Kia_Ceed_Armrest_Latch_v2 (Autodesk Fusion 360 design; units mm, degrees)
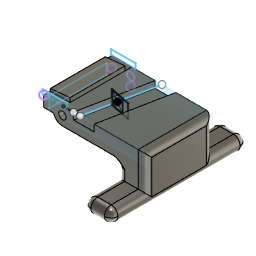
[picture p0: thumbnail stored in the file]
sketch "Sketch1" plane through (0, 0, 0) normal (0, 1, 0) x axis (1, 0, 0)
  line L1 (24.4506, -2.4661) -> (-5.5494, -2.4661)
  line L2 (24.4506, 0.6939) -> (24.4506, -2.4661)
  line L3 (-5.5494, 0.6939) -> (24.4506, 0.6939)
  line L4 (-5.5494, -2.4661) -> (-5.5494, 0.6939)
  line L5 (0.3006, -3.1561) -> (-5.5494, -3.1561)
  line L6 (0.3006, -2.4661) -> (0.3006, -3.1561)
  line L7 (-5.5494, -2.4661) -> (0.3006, -2.4661)
  line L8 (-5.5494, -3.1561) -> (-5.5494, -2.4661)
  line L9 (0.3006, -3.7461) -> (0.3006, -3.1561)
  line L10 (-5.5494, -3.1561) -> (0.3006, -3.7461)
  line L11 (16.4506, 7.6939) -> (24.4506, 7.6939)
  line L12 (4.3, 0.6939) -> (-3.0354, 0.6939)
  line L13 (4.3, -1.4) -> (4.3, 0.6939)
  line L14 (-3.0354, -1.4) -> (4.3, -1.4)
  line L15 (-3.0354, 0.6939) -> (-3.0354, -1.4)
  line L16 (24.4506, 7.6939) -> (16.4506, 7.6939)
  line L17 (24.4506, 11.6939) -> (24.4506, 7.6939)
  line L18 (16.4506, 11.6939) -> (24.4506, 11.6939)
  line L19 (16.4506, 7.6939) -> (16.4506, 11.6939)
  line L20 (24.4506, 9.6939) -> (24.4506, 0.6939)
  line L21 (24.9943, 2.7) -> (-0.0057, 2.7)
  line L22 (24.4506, 7.6939) -> (16.4506, 7.6939)
  line L23 (24.4506, 2.6939) -> (24.4506, 7.6939)
  line L24 (16.4506, 2.6939) -> (24.4506, 2.6939)
  line L25 (16.4506, 7.6939) -> (16.4506, 2.6939)
  circle C1 centre (0, 0) radius 2.7
  circle C2 centre (0, 0) radius 1.1
  point P1 (0, 0)
  point P13 (0, 0)
  point P14 (0, 0)
  point P15 (-3.0354, 0.6939)
  point P23 (-0.0057, 2.7)
  point P2 (-5.5494, -2.4661)
  point P3 (24.4506, -2.4661)
  point P5 (-5.5494, 0.6939)
  point P6 (-5.5494, -3.1561)
  point P7 (0.3006, -3.1561)
  point P9 (-5.5494, -2.4661)
  point P10 (0.3006, -3.7461)
  point P4 (24.4506, 0.6939)
  point P11 (24.4506, 7.6939)
  point P12 (16.4506, 7.6939)
  point P19 (24.4506, 7.6939)
  point P21 (16.4506, 11.6939)
  point P22 (24.4506, 9.6939)
  point P24 (24.9943, 2.7)
  point P25 (24.4506, 7.6939)
  point P27 (16.4506, 2.6939)
  horizontal L1
  vertical L2
  horizontal L3
  vertical L4
  horizontal L5
  vertical L6
  horizontal L7
  vertical L8
  perpendicular L5 L9
  coincident P1 P13
  coincident P1 P14
  horizontal L12
  vertical L13
  horizontal L14
  vertical L15
  coincident L3 P15
  horizontal L16
  vertical L17
  horizontal L18
  vertical L19
  perpendicular L3 L20
  coincident C1 P23
  perpendicular L20 L21
  horizontal L22
  vertical L23
  horizontal L24
  vertical L25
  dimension "d2" distance P2 P3 = 30
  dimension "d3" distance P2 P5 = 3.16
  dimension "d6" distance P6 P7 = 5.85
  dimension "d7" distance P6 P9 = 0.69
  dimension "d8" distance P7 P10 = 0.59
  dimension "d69" distance P4 P11 = 7
  dimension "d70" distance P11 P12 = 8
  dimension "d78" diameter C1 = 5.4
  dimension "d79" diameter C2 = 2.2
  dimension "d92" distance P12 P19 = 8
  dimension "d93" distance P12 P21 = 4
  dimension "d94" distance P4 P22 = 9
  dimension "d95" distance P23 P24 = 25
  dimension "d98" distance P12 P25 = 8
  dimension "d99" distance P12 P27 = 5
sketch "Sketch3" plane through (-5.5494, 0, 0) normal (-1, 0, 0) x axis (0, -1, 0)
  line L1 (-1.6288, 1.3075) -> (-18.6288, 1.3075)
  line L2 (-1.6288, -1.6925) -> (-1.6288, 1.3075)
  line L3 (-18.6288, -1.6925) -> (-1.6288, -1.6925)
  line L4 (-18.6288, 1.3075) -> (-18.6288, -1.6925)
  point P2 (-18.6288, 1.3075)
  point P3 (-1.6288, 1.3075)
  point P5 (-18.6288, -1.6925)
  horizontal L1
  vertical L2
  horizontal L3
  vertical L4
  dimension "d19" distance P2 P3 = 17
  dimension "d20" distance P2 P5 = 3
extrude "Extrude4" new body sketch "Sketch1" profile of L1 L2 L3 L4 L5 L6 L7 L8 L9 L10 along normal blind 20.21
extrude "Extrude5" cut sketch "Sketch3" against normal blind 3.81
sketch "Sketch6" plane through (0, 20.21, 0) normal (0, 1, 0) x axis (-1, 0, 0)
  line L1 (-24.4506, 2.4661) -> (5.5494, 2.4661)
  line L2 (-24.4506, -0.6939) -> (-24.4506, 2.4661)
  line L3 (5.5494, -0.6939) -> (-24.4506, -0.6939)
  line L4 (5.5494, 2.4661) -> (5.5494, -0.6939)
  line L5 (5.8, 2.4819) -> (-1.4771, 2.4819)
  line L6 (5.8, 4.0158) -> (5.8, 2.4819)
  line L7 (-1.4771, 4.0158) -> (5.8, 4.0158)
  line L8 (-1.4771, 2.4819) -> (-1.4771, 4.0158)
  horizontal L5
  vertical L6
  horizontal L7
  vertical L8
extrude "Extrude6" cut sketch "Sketch6" profile of L4 L5 L8 against normal blind 1.965
sketch "Sketch10" plane through (0, 0, 0) normal (0, -1, 0) x axis (1, 0, 0)
  line L1 (-5.5494, -0.6939) -> (-5.5494, 2.4661)
  line L2 (24.4506, -0.6939) -> (-5.5494, -0.6939)
  line L3 (24.4506, 2.4661) -> (24.4506, -0.6939)
  line L4 (-5.5494, 2.4661) -> (24.4506, 2.4661)
  line L5 (-5.8, 2.4819) -> (1.409, 2.4819)
  line L6 (-5.8, 3.8158) -> (-5.8, 2.4819)
  line L7 (1.409, 3.8158) -> (-5.8, 3.8158)
  line L8 (1.409, 2.4819) -> (1.409, 3.8158)
  horizontal L5
  vertical L6
  horizontal L7
  vertical L8
extrude "Extrude7" cut sketch "Sketch10" profile of L1 L5 L8 against normal blind 1.965
copy_paste_bodies "CopyPasteBodies1"
extrude "Extrude8" cut blind 40
extrude "Extrude11" new body sketch "Sketch1" + "Sketch10" profile of S1:L1 S1:L2 S1:L3 S1:L4 S1:L5 S1:L6 S1:L7 S1:L8 S1:L9 S1:L10 S2:L1 S2:L2 S2:L3 S2:L4 S2:L5 blind 20.21
extrude "Extrude12" cut sketch "Sketch3" against normal blind 3.24
extrude "Extrude13" cut blind 40
extrude "Extrude14" cut sketch "Sketch1" profile of L1 L5 L6 L7 L8 L9 L10 along normal blind 1.965
extrude "Extrude15" cut sketch "Sketch6" profile of L4 L5 L6 L7 L8 against normal blind 1.965
extrude "Extrude19" add sketch "Sketch1" profile of L3 C1 C2 L12 L13 L14 along normal blind 20.21
extrude "Extrude20" add sketch "Sketch1" profile of L3 C1 C2 L12 along normal blind 20.21
extrude "Extrude21" cut sketch "Sketch1" profile of L3 C2 L12 along normal blind 30
extrude "Extrude22" add sketch "Sketch3" against normal blind 4
extrude "Extrude23" cut sketch "Sketch3" against normal blind 3.45
extrude "Extrude24" add sketch "Sketch1" profile of L3 C1 L12 L20 L21 along normal blind 20.21
extrude "Extrude25" add sketch "Sketch1" profile of L11 L16 L20 L21 L22 L23 L25 along normal blind 20.21
extrude "Extrude26" new body sketch "Sketch1" profile of L11 L16 L17 L18 L19 L20 L22 against normal blind 10
extrude "Extrude27" add sketch "Sketch1" profile of L11 L16 L17 L18 L19 L20 L22 along normal blind 20.21
extrude "Extrude28" add of existing geometry blind 10
extrude "Extrude29" cut sketch "Sketch1" profile of L3 C2 L12 along normal blind 60
copy_paste_bodies "CopyPasteBodies1"
copy_paste_bodies "CopyPasteBodies2"
copy_paste_bodies "CopyPasteBodies3"
copy_paste_bodies "CopyPasteBodies4"
combine "Combine1"
fillet "Fillet1" radius 2
sketch "Sketch13" plane through (0, 0, 0) normal (0, 1, 0) x axis (1, 0, 0)
sketch "Sketch14" plane through (0, 20.21, 0) normal (0, 1, 0) x axis (-1, 0, 0)
  line L1 (-0.0033, -2.7) -> (-14.9865, -2.7)
  line L2 (5.5494, -0.6939) -> (2.6093, -0.6939)
  line L3 (5.5494, 2.4819) -> (5.5494, -0.6939)
  line L4 (-0.3006, 2.4819) -> (5.5494, 2.4819)
  line L5 (-0.3006, 2.4661) -> (-0.3006, 2.4819)
  line L6 (-22.4506, 2.4661) -> (-0.3006, 2.4661)
  line L7 (-22.4506, -7.6939) -> (-22.4506, 2.4661)
  line L8 (-18.4506, -7.6939) -> (-22.4506, -7.6939)
  line L9 (-18.4506, -4.7) -> (-18.4506, -7.6939)
  curve K1 (-18.4506, -4.7) -> (-14.9865, -2.7)
  arc A1 centre (0, 0) radius 2.7 clockwise from (2.6093, -0.6939) to (-0.0033, -2.7)
  circle C1 centre (0, 0) radius 1.1
sketch "Sketch15" plane through (0, 0, 2.4661) normal (0, 0, 1) x axis (-1, 0, 0)
  line L1 (-22.4506, -20.21) -> (-22.4506, 0)
  line L2 (-0.3006, -20.21) -> (-22.4506, -20.21)
  line L3 (-0.3006, -1.965) -> (-0.3006, -20.21)
  line L4 (5.5494, -1.965) -> (-0.3006, -1.965)
  line L5 (5.5494, 0) -> (5.5494, -1.965)
  line L6 (-22.4506, 0) -> (5.5494, 0)
  line L7 (-3.3006, 0) -> (-0.3006, 0)
  line L8 (-9.3006, -20.21) -> (-5.3006, 0)
  point P8 (-0.3006, 0)
  point P9 (-3.3006, 0)
  point P10 (-5.3006, 0)
  coincident L6 P8
  perpendicular L3 L7
  dimension "d117" distance P8 P9 = 3
  dimension "d118" distance P9 P10 = 2
work_plane "WorkPlane1" PathDistance 0.5601
sketch "Sketch16" plane through (7.1141, 9.1626, 2.4661) normal (0.1942, 0.981, 0) x axis (-0.981, 0.1942, 0)
  line L1 (2, 2) -> (-2, 2)
  line L2 (2, -2) -> (2, 2)
  line L3 (-2, -2) -> (2, -2)
  line L4 (-2, 2) -> (-2, -2)
  line L5 (2, -2) -> (-2, 2)
  line L6 (-2, -2) -> (2, 2)
  line L7 (-4, 2) -> (2, 2)
  line L8 (-4, -2) -> (-4, 2)
  line L9 (2, -2) -> (-4, -2)
  line L10 (2, 2) -> (2, -2)
  point P6 (0, 0)
  point P1 (0, 0)
  point P4 (2, -2)
  point P5 (-2, -2)
  point P3 (2, 2)
  point P7 (-4, 2)
  point P9 (2, -2)
  horizontal L1
  perpendicular L1 L2
  parallel L1 L3
  parallel L2 L4
  coincident L5 P6
  coincident L6 P6
  coincident P1 P6
  horizontal L7
  vertical L8
  horizontal L9
  vertical L10
  dimension "d121" distance P4 P5 = 4
  dimension "d122" distance P3 P4 = 4
  dimension "d123" distance P3 P7 = 6
  dimension "d124" distance P3 P9 = 4
extrude "Extrude1" cut sketch "Sketch16" profile of L1 L2 L3 L4 L7 L8 L9 L10 distance 15
extrude "Extrude2" add sketch "Sketch1" profile of L3 C2 L12 along normal blind 20.21
extrude "Extrude3" cut sketch "Sketch1" profile of L3 C2 L12 along normal blind 20.21
extrude "Extrude4" add sketch "Sketch1" profile of L3 C2 L12 along normal blind 20.21
extrude "Extrude5" cut sketch "Sketch1" profile of L3 C2 L12 along normal blind 20.21
extrude "Extrude16" add sketch "Sketch1" profile of L3 L11 along normal blind 20.21
extrude "Extrude17" cut sketch "Sketch3" against normal blind 3.8
extrude "Extrude18" add sketch "Sketch1" profile of L1 L3 L7 along normal blind 20.21
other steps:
base_feature "Base Feature1"
base_feature "Base Feature2"
base_feature "Base Feature3"
base_feature "Base Feature4"
base_feature "Base Feature1"
fillet "Fillet1" radius 2
create_component "CreateComponent1"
